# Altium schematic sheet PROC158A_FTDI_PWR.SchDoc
size 431 x 279 mm; Date: Not shown in title block; ApprovedBy: Not shown in title block; CheckedBy: Not shown in title block; Author: Not shown in title block; CompanyName: Not shown in title block; Engineer: Not shown in title block; Organization: Not shown in title block; Address1: Not shown in title block; Address2: Not shown in title block; Address3: Not shown in title block; Address4: Not shown in title block; DocumentNumber: 16; Revision: Use project parameter SCH_Rev; SheetNumber: 16; SheetTotal: 24; PageSetup: Record=PageOptions¦CenterHorizontal=True¦CenterVertical=True¦PrintScale=1.00¦XCorrection=1.00¦YCorrection=1.00¦PrintKind=0¦BorderSize=5000000¦LeftOffset=0¦BottomOffset=0¦Orientation=2¦PaperLength=1000¦PaperWidth=1000¦Scale=100¦PaperSource=15¦PrintQuality=600¦MediaType=1¦DitherType=10¦PaperKind=Letter¦PrintScaleMode=1
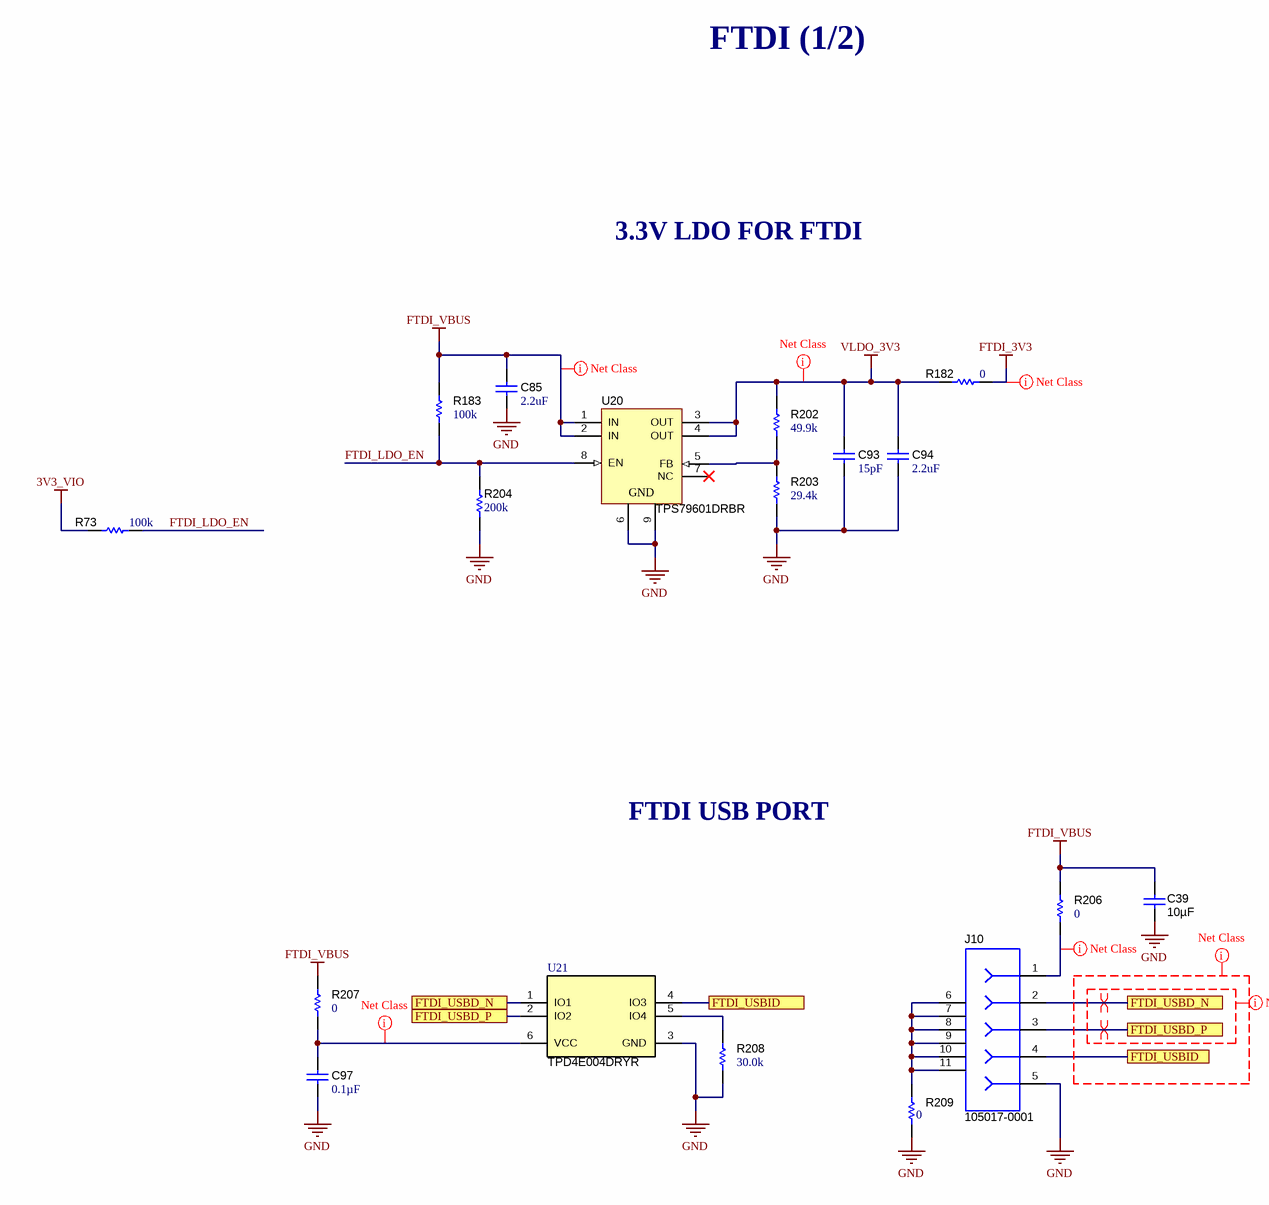
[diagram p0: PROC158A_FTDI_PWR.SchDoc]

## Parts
C39  Cap_F: 10µF  [0805L]  (hidden comment: CL21B106KOQNNNE)
C85  ValueDisplayed: 2.2uF  [0402_065L]  (hidden comment: C1005X7S1A225K050BC)
C93  ValueDisplayed: 15pF  [0402L]  (hidden comment: 04025A150FAT2A)
C94  ValueDisplayed: 2.2uF  [0402_065L]  (hidden comment: C1005X7S1A225K050BC)
C97  ValueDisplayed: 0.1µF  [0402L]  (hidden comment: C0402C104K8RACTU)
J10  105017-0001  [CONN_105017-0001]
R73  ValueDisplayed: 100k  [0402L]  (hidden comment: CRCW0402100KFKED)
R182  ValueDisplayed: 0  [0805L]  (hidden comment: CRCW08050000Z0EA)
R183  ValueDisplayed: 100k  [0402L]  (hidden comment: CRCW0402100KFKED)
R202  ValueDisplayed: 49.9k  [0402L]  (hidden comment: CRCW040249K9FKED)
R203  ValueDisplayed: 29.4k  [0402L]  (hidden comment: CRCW040229K4FKED)
R204  ValueDisplayed: 200k  [0402L]  (hidden comment: CRCW0402200KFKED)
R206  ValueDisplayed: 0  [0805L]  (hidden comment: CRCW08050000Z0EA)
R207  ValueDisplayed: 0  [0805L]  (hidden comment: CRCW08050000Z0EA)
R208  ValueDisplayed: 30.0k  [0402L]  (hidden comment: CRCW040230K0FKED)
R209  ValueDisplayed: 0  [0402L]  (hidden comment: ERJ-2GE0R00X)
U20  TPS79601DRBR  [DRB0008B]
U21  TPD4E004DRYR  [DRY0006A]

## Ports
FTDI_USBD_N, FTDI_USBD_P, FTDI_USBID

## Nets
3V3_VIO: R73.2
FTDI_3V3: R182.2
FTDI_VBUS: C39.1 C85.1 R183.2 R206.2 R207.2 U20.1(IN) U20.2(IN)
GND: C39.2 C85.2 C93.2 C94.2 C97.2 J10.5 R203.2 R204.1 R208.1 R209.1 U20.6(GND) U20.9(GND) U21.3(GND)
VLDO_3V3: C93.1 C94.1 R182.1 R202.2 U20.3(OUT) U20.4(OUT)
FTDI_LDO_EN: R73.1 R183.1 R204.2 U20.8(EN)
FTDI_USBD_N: J10.2 U21.1(IO1) ; port FTDI_USBD_N
FTDI_USBD_P: J10.3 U21.2(IO2) ; port FTDI_USBD_P
FTDI_USBID: J10.4 U21.4(IO3) ; port FTDI_USBID
NetC97_1: C97.1 R207.1 U21.6(VCC)
NetJ10_1: J10.1 R206.1
NetJ10_6: J10.6 J10.7 J10.8 J10.9 J10.10 J10.11 R209.2
NetR202_1: R202.1 R203.1 U20.5(FB)
NetR208_2: R208.2 U21.5(IO4)

Not connected (* = marked no-connect by the designer): U20 7(NC)*

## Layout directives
net class FTDI_USB: (no net found under the mark)
net class PWR: FTDI_3V3, FTDI_VBUS, NetC97_1, NetJ10_1, VLDO_3V3
differential pair: FTDI_USBD_N, FTDI_USBD_P
net class USB_DIFF: (no net found under the mark)

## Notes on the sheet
- FTDI (1/2)
- 3.3V LDO FOR FTDI
- FTDI USB PORT

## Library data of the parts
C39 = CMP-0007995-2: CAP, CERM, 10 uF, 16 V, +/- 10%, X7R, 0805; Manufacturer: Samsung Electro-Mechanics; TaMin_C: -55°C; Polarized: N; SizeAreaWB_mm2: 6.75; Value1: Unknown; U/M: EA; Value: 10uF; TaMax_C: 125°C; SizeZ_mm: 1.45; SizeX_mm: 2; SizeY_mm: 1.25; Cap_Case: 0805; Value2: 16V; SizeArea_mm2: 2.5; AEC Category: Q200
C85 C94 = CMP-0006302-2: CAP, CERM, 2.2 uF, 10 V, +/- 10%, X7S, 0402; Manufacturer: TDK; TaMin_C: -55°C; ESR_ohm: 5.925m; Polarized: N; SizeAreaWB_mm2: 3; Value1: 0.005925 ohm; U/M: EA; Value: 2.2uF; TaMax_C: 125°C; SizeZ_mm: 0.65; SizeX_mm: 1; SizeY_mm: 0.5; Cap_Case: 0402_065; Value2: 10V; CompType: Capacitor; Cap_F: 2.2µF; IRMS_A: 2.05591A; AEC Category: Q200
C93 = CMP-0078217-1: CAP, CERM, 15 pF, 50 V,+/- 1%, C0G/NP0, 0402; Manufacturer: AVX; TaMin_C: -55°C; Polarized: N; Green_Lifecycle: Not Set; SizeAreaWB_mm2: 3; Green_REACh: Incomplete; U/M: EA; Value: 15pF; TaMax_C: 125°C; SizeZ_mm: 0.6; SizeX_mm: 1; SizeY_mm: 0.5; Cap_Case: 0402; Value2: 50V; AEC Category: Q200
C97 = CMP-0078241-1: CAP, CERM, 0.1 µF, 10 V,+/- 10%, X7R, 0402; Manufacturer: Kemet; TaMin_C: -55°C; Polarized: N; SizeAreaWB_mm2: 3; U/M: EA; Value: 0.1uF; TaMax_C: 125°C; SizeZ_mm: 0.6; SizeX_mm: 1; SizeY_mm: 0.5; Cap_Case: 0402; Value2: 10V; Cap_F: 100nF; AEC Category: Q200
J10 = CMP-0055293-1: Connector, Receptacle, Micro-USB Type B, R/A, Bottom Mount SMT; Manufacturer: Molex; CNHeader: FALSE; Green_Lifecycle: Active; Gender: Female; Green_REACh: Passed; CompType: USB; CT: TRUE
R73 R183 = CMP-0025950-3: RES, 100 k, 1%, 0.063 W, AEC-Q200 Grade 0, 0402; Manufacturer: Vishay-Dale; Power_W: 63mW; TempCo: 100 ppm/C; Value: 100k; EIA_Code: E96; SizeX_mm: 1; SizeY_mm: 0.5; SizeZ_mm: 0.6; Value2: 0.063W; CompType: Resistor; AEC Qualified: Y; VDC_V: 50V; AEC Category: Q200; AEC Grade: 0; INSTALLATION: DNP
R182 R206 R207 = CMP-0020442-3: RES, 0, 5%, 0.125 W, AEC-Q200 Grade 0, 0805; Manufacturer: Vishay-Dale; Power_W: 125mW; TempCo: 200 ppm/C; Value_Code: 0000; Value: 0; EIA_Code: E24; SizeX_mm: 2; SizeY_mm: 1.25; SizeZ_mm: 1.45; Value2: 0.125W; SizeArea_mm2: 2.5; AEC Qualified: Y; VDC_V: 150V; AEC Category: Q200
R202 = CMP-0026403-2: RES, 49.9 k, 1%, 0.063 W, AEC-Q200 Grade 0, 0402; Manufacturer: Vishay-Dale; Power_W: 63mW; TempCo: 100 ppm/C; Value_Code: 49k9; Value: 49.9k; EIA_Code: E96; SizeX_mm: 1; SizeY_mm: 0.5; SizeZ_mm: 0.6; Value2: 0.063W; AEC Qualified: Y; VDC_V: 50V; AEC Category: Q200; AEC Grade: 0
R203 = CMP-0026225-2: RES, 29.4 k, 1%, 0.063 W, AEC-Q200 Grade 0, 0402; Manufacturer: Vishay-Dale; Power_W: 63mW; TempCo: 100 ppm/C; Value_Code: 29k4; Value: 29.4k; EIA_Code: E96; SizeX_mm: 1; SizeY_mm: 0.5; SizeZ_mm: 0.6; Value2: 0.063W; AEC Qualified: Y; VDC_V: 50V; AEC Category: Q200; AEC Grade: 0
R204 = CMP-0026158-2: RES, 200 k, 1%, 0.063 W, AEC-Q200 Grade 0, 0402; Manufacturer: Vishay-Dale; Power_W: 63mW; TempCo: 100 ppm/C; Value: 200k; EIA_Code: E96; SizeX_mm: 1; SizeY_mm: 0.5; SizeZ_mm: 0.6; Value2: 0.063W; AEC Qualified: Y; VDC_V: 50V; AEC Category: Q200; AEC Grade: 0
R208 = CMP-0078244-2: RES, 30.0 k, 1%, 0.063 W, AEC-Q200 Grade 0, 0402; Manufacturer: Vishay-Dale; Power_W: 63mW; Green_Lifecycle: Active; TempCo: 100 ppm/C; Value_Code: 30k0; Green_REACh: Passed; Value: 30.0k; Res_ohm: 30k; SizeX_mm: 1; SizeY_mm: 0.5; SizeZ_mm: 0.6; Value2: 0.063W; AEC Qualified: Y; VDC_V: 50V; AEC Grade: 0; AEC Category: Q200
R209 = CMP-0026992-3: RES, 0, 5%, 0.1 W, AEC-Q200 Grade 0, 0402; Manufacturer: Panasonic; Power_W: 100mW; TempCo: 600 ppm/C; Value_Code: 0000; Value: 0; EIA_Code: E24; SizeX_mm: 1; SizeY_mm: 0.5; SizeZ_mm: 0.6; Value2: 0.1W; AEC Qualified: Y; VDC_V: 50V; AEC Category: Q200; SizeAreaWB_mm2: 3
U20 = CMP-0036402-3: Single Output High PSRR LDO, 1 A, Adjustable 1.2 to 5.5 V Output, 2.7 to 5.5 V Input, 8-pin SON (DRB), -40 to 125 degC, Green (RoHS & no Sb/Br); Manufacturer: Texas Instruments; Vin(Min)(V): 2.7; Vout Adj(Max)(V): 5.5; Vout Adj(Min)(V): 1.2; Accuracy(%): 2; SubFamily: Single Channel LDO; Iq(Typ)(mA): 0.26; Vdo(Typ)(mV): 250; Iout(Max)(A): 1; AEC Category: Q200; AEC Qualified: N; CompType: IC; SizeAreaWB_mm2: 16.0; SizeArea_mm2: 9.0; SizeX_mm: 3.0; SizeZ_mm: 1.0
U21 = CMP-0043115-3: 4-Channel ESD Protection Array for High-Speed Data Interfaces, DRY0006A (USON-6); Manufacturer: Texas Instruments; IO Leakage Current(nA): 1; USB High Speed: TRUE; IO Capacitance(Typ)(pF): 1.6; Eco-Plan: Green (RoHS & no Sb/Br); IEC 61000-4-2 Contact(+/- kV): 8; Breakdown Voltage(Min)(V): 6; IEC 61000-4-2 Air-Gap(+/- kV): 12; AEC Category: Q200; AEC Qualified: N; CompType: IC; SizeAreaWB_mm2: 4.9; SizeArea_mm2: 1.45; SizeX_mm: 1.0; SizeZ_mm: 0.6; Rating: Catalog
